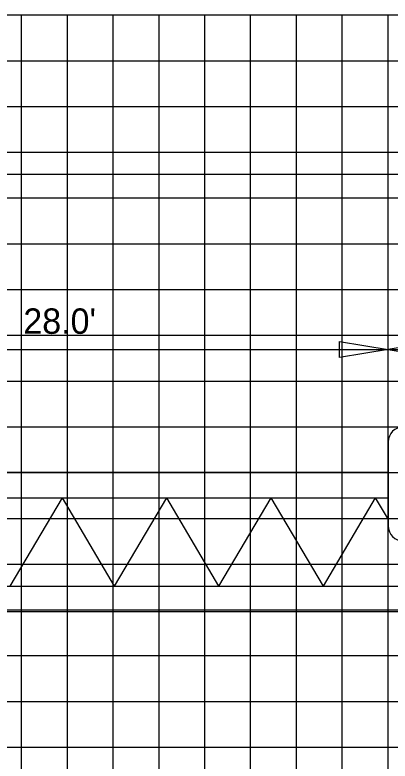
# Model space of a CAD drawing. Extents: x 2193008 to 2198143, y 1236112 to 1237864.
# Drawn here: x 2195596.41 to 2195612.8, y 1237190.5 to 1237223.11 of the extents above; entities that cross this region are included whole.
import ezdxf

# ---------------------------------------------------------------- set-up
doc = ezdxf.new("R2010")
doc.units = 0
for name, color, linetype in [('3', 7, 'Continuous'), ('GSCOLORFILL', 7, 'Continuous'), ('GSDIMS', 7, 'Continuous'), ('Level 55', 7, 'Continuous'), ('M-ROADS', 7, 'Continuous')]:
    doc.layers.add(name, color=color, linetype=linetype)

msp = doc.modelspace()

# ---------------------------------------------------------------- linework, layer by layer
at = {"layer": '3'}
msp.add_line((2195584.245, 1237216.154), (2195679.319, 1237216.154), dxfattribs=at)
at = {"layer": 'GSCOLORFILL'}
msp.add_line((2195612.713, 1237204.44), (2195612.713, 1237200.777), dxfattribs=at)
for centre, start, end in [((2195613.379, 1237204.44), 90, 180), ((2195613.379, 1237200.777), 180, 270)]:
    msp.add_arc(centre, 0.666, start, end, dxfattribs=at)
at = {"layer": 'GSDIMS'}
for p, q in [((2195612.713, 1237207.499), (2195612.713, 1237209.24)), ((2195584.707, 1237208.482), (2195612.713, 1237208.482)), ((2195612.713, 1237208.482), (2195627.199, 1237208.482)), ((2195585.245, 1237203.12), (2195612.713, 1237203.12)), ((2195585.245, 1237202.009), (2195612.713, 1237202.009)), ((2195598.475, 1237202.009), (2195596.197, 1237198.147)), ((2195598.475, 1237202.009), (2195600.754, 1237198.147)), ((2195603.032, 1237202.009), (2195600.754, 1237198.147)), ((2195603.032, 1237202.009), (2195605.311, 1237198.147)), ((2195607.59, 1237202.009), (2195605.311, 1237198.147)), ((2195607.59, 1237202.009), (2195609.868, 1237198.147)), ((2195612.147, 1237202.009), (2195609.868, 1237198.147)), ((2195612.147, 1237202.009), (2195612.713, 1237201.049)), ((2195585.245, 1237198.147), (2195614.457, 1237198.147)), ((2195585.245, 1237197.036), (2195614.457, 1237197.036))]:
    msp.add_line(p, q, dxfattribs=at)
for points in [[(2195612.713, 1237208.482), (2195610.585, 1237208.135), (2195610.585, 1237208.829)], [(2195612.713, 1237208.482), (2195614.842, 1237208.135), (2195614.842, 1237208.829)]]:
    msp.add_lwpolyline(points, close=True, dxfattribs=at)
at = {"layer": 'M-ROADS'}
for p, q in [((2195584.707, 1237223.106), (2195714.707, 1237223.106)), ((2195596.707, 1237163.106), (2195596.707, 1237223.106)), ((2195598.707, 1237163.106), (2195598.707, 1237223.106)), ((2195600.707, 1237163.106), (2195600.707, 1237223.106)), ((2195602.707, 1237163.106), (2195602.707, 1237223.106)), ((2195604.707, 1237163.106), (2195604.707, 1237223.106)), ((2195606.707, 1237163.106), (2195606.707, 1237223.106)), ((2195608.707, 1237163.106), (2195608.707, 1237223.106)), ((2195610.707, 1237163.106), (2195610.707, 1237223.106)), ((2195612.707, 1237163.106), (2195612.707, 1237223.106)), ((2195584.707, 1237221.106), (2195714.707, 1237221.106)), ((2195584.707, 1237219.106), (2195714.707, 1237219.106)), ((2195584.707, 1237217.106), (2195714.707, 1237217.106)), ((2195584.707, 1237215.106), (2195714.707, 1237215.106)), ((2195584.707, 1237213.106), (2195714.707, 1237213.106)), ((2195584.707, 1237211.106), (2195714.707, 1237211.106)), ((2195584.707, 1237209.106), (2195714.707, 1237209.106)), ((2195584.707, 1237207.106), (2195714.707, 1237207.106)), ((2195584.707, 1237205.106), (2195714.707, 1237205.106)), ((2195584.707, 1237203.106), (2195714.707, 1237203.106)), ((2195584.707, 1237201.106), (2195714.707, 1237201.106)), ((2195584.707, 1237199.106), (2195714.707, 1237199.106)), ((2195584.707, 1237197.106), (2195714.707, 1237197.106)), ((2195584.707, 1237195.106), (2195714.707, 1237195.106)), ((2195584.707, 1237193.106), (2195714.707, 1237193.106)), ((2195584.707, 1237191.106), (2195714.707, 1237191.106))]:
    msp.add_line(p, q, dxfattribs=at)

# ---------------------------------------------------------------- texts
at = {"layer": 'Level 55'}
msp.add_text("28.0'", height=1.1105, dxfattribs=at).set_placement((2195596.781, 1237209.17))

doc.saveas('drawing.dxf')
